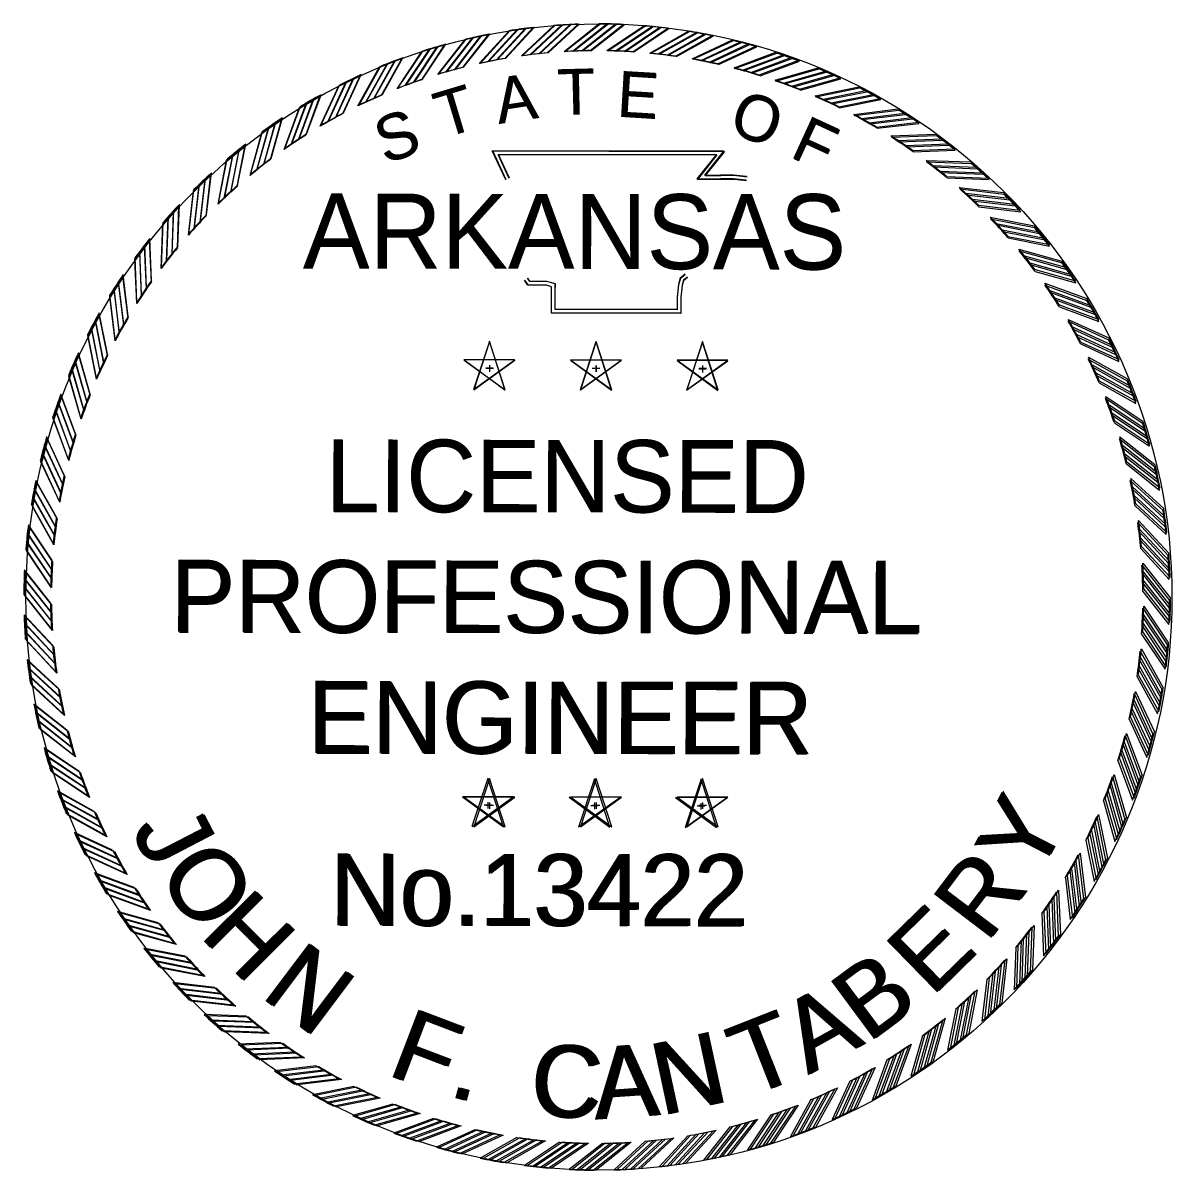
# Model space of a CAD drawing. Extents: x 759422 to 1467391, y 1662254 to 1691810.
# Drawn here: x 1467270.3 to 1467390.6, y 1691457.7 to 1691577.8 of the extents above; entities that cross this region are included whole.
import ezdxf

# ---------------------------------------------------------------- set-up
doc = ezdxf.new("R2010")
doc.units = 0
for name, color, linetype in [('Default', 7, 'Continuous'), ('G-ANNO-STMP', 7, 'Continuous'), ('G-No Plot-Stamp-1', 7, 'Continuous')]:
    doc.layers.add(name, color=color, linetype=linetype)

# ---------------------------------------------------------------- blocks, each defined once
blk = doc.blocks.new('STAR')
at = {"layer": 'Default'}
for p, q in [((-0.0001, 0.0615), (-0.0366, -0.0504)), ((0.0362, -0.0503), (0, 0.0617)), ((0.0587, 0.0188), (-0.059, 0.0189)), ((-0.0589, 0.0188), (0.0363, -0.0505)), ((-0.0365, -0.0503), (0.0589, 0.0188)), ((-0.0085, 0), (0.009, 0)), ((0, 0.0063), (0, -0.0085))]:
    blk.add_line(p, q, dxfattribs=at)
blk = doc.blocks.new('RP')
at = {"layer": 'Default'}
for p, q in [((-0.0781, 1.2656), (0.003, 1.33)), ((-0.058, 1.2667), (0.0216, 1.3299)), ((-0.0375, 1.2674), (0.0405, 1.3294)), ((-0.0176, 1.2679), (0.059, 1.3287))]:
    blk.add_line(p, q, dxfattribs=at)
for radius, start, end in [(1.33, 87.4562, 89.8699), (1.268, 90.7933, 93.5307)]:
    blk.add_arc((0, 0), radius, start, end, dxfattribs=at)

msp = doc.modelspace()

# ---------------------------------------------------------------- linework, layer by layer
at = {"layer": 'G-ANNO-STMP'}
for points in [[(1467320.82, 1691561.41), (1467319.42, 1691564.45), (1467343.68, 1691564.46), (1467341.65, 1691561.91), (1467343.3, 1691561.93), (1467344.67, 1691561.95), (1467346.05, 1691561.8)], [(1467320.86, 1691561.43), (1467319.47, 1691564.47), (1467343.73, 1691564.4), (1467341.7, 1691561.86), (1467343.35, 1691561.87), (1467344.72, 1691561.89), (1467346.1, 1691561.73)], [(1467321.17, 1691561.57), (1467320.02, 1691564.06), (1467342.88, 1691564.07), (1467340.84, 1691561.52), (1467343.3, 1691561.55), (1467344.65, 1691561.57), (1467346.01, 1691561.42)], [(1467321.21, 1691561.59), (1467320.07, 1691564.08), (1467342.93, 1691564.02), (1467340.89, 1691561.47), (1467343.35, 1691561.49), (1467344.7, 1691561.5), (1467346.05, 1691561.35)], [(1467339.85, 1691551.24), (1467339.44, 1691550.91), (1467339.3, 1691550.4), (1467339.16, 1691549.14), (1467339.16, 1691547.47), (1467325.62, 1691547.47), (1467325.62, 1691549.73), (1467325.62, 1691550.23), (1467325.07, 1691550.4), (1467323.15, 1691550.4), (1467322.8, 1691550.92)], [(1467339.87, 1691551.19), (1467339.45, 1691550.86), (1467339.31, 1691550.36), (1467339.17, 1691549.1), (1467339.16, 1691547.42), (1467325.62, 1691547.47), (1467325.63, 1691549.73), (1467325.63, 1691550.23), (1467325.08, 1691550.4), (1467323.16, 1691550.41), (1467322.82, 1691550.93)], [(1467339.61, 1691551.54), (1467339.1, 1691551.13), (1467338.92, 1691550.47), (1467338.78, 1691549.17), (1467338.78, 1691547.85), (1467326.01, 1691547.85), (1467326.01, 1691549.73), (1467326.01, 1691550.52), (1467325.13, 1691550.79), (1467323.35, 1691550.79), (1467323.12, 1691551.14)], [(1467339.62, 1691551.49), (1467339.11, 1691551.08), (1467338.93, 1691550.43), (1467338.79, 1691549.12), (1467338.78, 1691547.81), (1467326.01, 1691547.85), (1467326.01, 1691549.73), (1467326.02, 1691550.52), (1467325.14, 1691550.79), (1467323.36, 1691550.79), (1467323.14, 1691551.14)]]:
    msp.add_lwpolyline(points, dxfattribs=at)
at = {"layer": 'G-No Plot-Stamp-1'}
msp.add_circle((1467330.59, 1691517.75), 60, dxfattribs=at)

# ---------------------------------------------------------------- block references
at = {"layer": 'G-ANNO-STMP'}
for name, p, xscale, yscale, rotation in [('RP', (1467330.45, 1691517.76), 45.10357918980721, 45.10357918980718, 4.500000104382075), ('RP', (1467330.35, 1691517.74), 45.1035791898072, 45.10357918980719, 4.304199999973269), ('RP', (1467330.45, 1691517.76), 45.1035791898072, 45.10357918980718, 1.0438208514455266e-07), ('RP', (1467330.35, 1691517.74), 45.1035791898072, 45.10357918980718, -0.19580000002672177), ('RP', (1467330.45, 1691517.76), 45.103579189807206, 45.10357918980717, -4.499999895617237), ('RP', (1467330.35, 1691517.74), 45.103579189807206, 45.10357918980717, -4.695800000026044), ('RP', (1467330.45, 1691517.76), 45.10357918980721, 45.103579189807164, -8.999999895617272), ('RP', (1467330.35, 1691517.74), 45.10357918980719, 45.103579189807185, -9.19580000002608), ('RP', (1467330.45, 1691517.76), 45.10357918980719, 45.10357918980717, 13.500000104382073), ('RP', (1467330.35, 1691517.74), 45.1035791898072, 45.103579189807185, 13.304199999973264), ('RP', (1467330.45, 1691517.76), 45.103579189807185, 45.103579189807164, 9.000000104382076), ('RP', (1467330.35, 1691517.74), 45.10357918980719, 45.103579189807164, 8.804199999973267), ('RP', (1467330.45, 1691517.76), 45.10357918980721, 45.10357918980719, -13.499999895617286), ('RP', (1467330.35, 1691517.74), 45.103579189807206, 45.103579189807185, -13.695800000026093), ('RP', (1467330.45, 1691517.76), 45.103579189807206, 45.10357918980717, 18.00000010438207), ('RP', (1467330.35, 1691517.74), 45.1035791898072, 45.10357918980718, 17.804199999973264), ('RP', (1467330.45, 1691517.76), 45.103579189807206, 45.103579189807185, -17.999999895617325), ('RP', (1467330.35, 1691517.74), 45.1035791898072, 45.10357918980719, -18.19580000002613), ('RP', (1467330.45, 1691517.76), 45.1035791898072, 45.10357918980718, 22.500000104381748), ('RP', (1467330.35, 1691517.74), 45.1035791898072, 45.10357918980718, 22.304199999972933), ('RP', (1467330.45, 1691517.76), 45.103579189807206, 45.10357918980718, -22.499999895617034), ('RP', (1467330.35, 1691517.74), 45.10357918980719, 45.103579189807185, -22.695800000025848), ('RP', (1467330.45, 1691517.76), 45.10357918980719, 45.103579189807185, -26.999999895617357), ('RP', (1467330.35, 1691517.74), 45.1035791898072, 45.10357918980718, -27.19580000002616), ('RP', (1467330.45, 1691517.76), 45.1035791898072, 45.10357918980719, 27.000000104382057), ('RP', (1467330.35, 1691517.74), 45.1035791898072, 45.103579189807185, 26.80419999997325), ('RP', (1467330.45, 1691517.76), 45.10357918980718, 45.103579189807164, 31.50000010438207), ('RP', (1467330.35, 1691517.74), 45.10357918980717, 45.103579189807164, 31.30419999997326), ('RP', (1467330.45, 1691517.76), 45.10357918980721, 45.1035791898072, -31.49999989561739), ('RP', (1467330.35, 1691517.74), 45.103579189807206, 45.1035791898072, -31.695800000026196), ('RP', (1467330.45, 1691517.76), 45.10357918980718, 45.103579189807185, 36.00000010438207), ('RP', (1467330.35, 1691517.74), 45.10357918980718, 45.10357918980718, 35.804199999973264), ('RP', (1467330.45, 1691517.76), 45.10357918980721, 45.10357918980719, -35.999999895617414), ('RP', (1467330.35, 1691517.74), 45.1035791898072, 45.10357918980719, -36.195800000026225), ('RP', (1467330.45, 1691517.76), 45.1035791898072, 45.1035791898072, -40.49999989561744), ('RP', (1467330.35, 1691517.74), 45.1035791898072, 45.10357918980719, -40.69580000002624), ('RP', (1467330.45, 1691517.76), 45.103579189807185, 45.10357918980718, 40.50000010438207), ('RP', (1467330.35, 1691517.74), 45.103579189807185, 45.10357918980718, 40.30419999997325), ('RP', (1467330.45, 1691517.76), 45.10357918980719, 45.10357918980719, 45.00000010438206), ('RP', (1467330.35, 1691517.74), 45.103579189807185, 45.10357918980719, 44.80419999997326), ('RP', (1467330.45, 1691517.76), 45.1035791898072, 45.10357918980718, -44.99999989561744), ('RP', (1467330.35, 1691517.74), 45.103579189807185, 45.10357918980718, -45.19580000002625), ('RP', (1467330.45, 1691517.76), 45.10357918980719, 45.103579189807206, 49.500000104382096), ('RP', (1467330.35, 1691517.74), 45.103579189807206, 45.1035791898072, 49.304199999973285), ('RP', (1467330.45, 1691517.76), 45.103579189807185, 45.10357918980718, -49.499999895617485), ('RP', (1467330.35, 1691517.74), 45.10357918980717, 45.103579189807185, -49.695800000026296), ('RP', (1467330.45, 1691517.76), 45.10357918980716, 45.10357918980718, -53.999999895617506), ('RP', (1467330.45, 1691517.76), 45.103579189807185, 45.10357918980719, 54.00000010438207), ('RP', (1467330.35, 1691517.74), 45.10357918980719, 45.103579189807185, 53.804199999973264), ('RP', (1467330.35, 1691517.74), 45.103579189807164, 45.10357918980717, -54.1958000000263), ('RP', (1467330.35, 1691517.74), 45.10357918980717, 45.103579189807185, 58.304199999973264), ('RP', (1467330.45, 1691517.76), 45.10357918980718, 45.10357918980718, 58.50000010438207), ('RP', (1467330.45, 1691517.76), 45.103579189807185, 45.10357918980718, -58.49999989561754), ('RP', (1467330.35, 1691517.74), 45.10357918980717, 45.103579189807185, -58.695800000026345), ('RP', (1467330.35, 1691517.74), 45.103579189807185, 45.103579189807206, 62.804199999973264), ('RP', (1467330.45, 1691517.76), 45.10357918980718, 45.10357918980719, -62.99999989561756), ('RP', (1467330.35, 1691517.74), 45.103579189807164, 45.10357918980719, -63.19580000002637), ('RP', (1467330.45, 1691517.76), 45.10357918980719, 45.1035791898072, 63.000000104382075), ('STAR', (1467319.11, 1691541.73), 45.1035791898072, 45.10357918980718, -0.19580000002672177), ('STAR', (1467319.13, 1691541.71), 45.1035791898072, 45.10357918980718, 1.0438208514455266e-07), ('STAR', (1467330.27, 1691541.69), 45.1035791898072, 45.10357918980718, -0.19580000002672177), ('STAR', (1467330.29, 1691541.71), 45.1035791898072, 45.10357918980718, 1.0438208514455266e-07), ('STAR', (1467341.42, 1691541.65), 45.1035791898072, 45.10357918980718, -0.19580000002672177), ('STAR', (1467341.44, 1691541.71), 45.1035791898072, 45.10357918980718, 1.0438208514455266e-07), ('RP', (1467330.45, 1691517.76), 45.10357918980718, 45.1035791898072, -67.49999989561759), ('RP', (1467330.35, 1691517.74), 45.10357918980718, 45.1035791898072, 67.30419999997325), ('RP', (1467330.45, 1691517.76), 45.10357918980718, 45.103579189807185, 67.50000010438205), ('RP', (1467330.35, 1691517.74), 45.10357918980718, 45.103579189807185, -67.69580000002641), ('RP', (1467330.35, 1691517.74), 45.103579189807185, 45.1035791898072, 71.80419999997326), ('RP', (1467330.35, 1691517.74), 45.10357918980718, 45.1035791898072, -72.19580000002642), ('RP', (1467330.45, 1691517.76), 45.10357918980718, 45.1035791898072, -71.99999989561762), ('RP', (1467330.45, 1691517.76), 45.103579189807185, 45.10357918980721, 72.00000010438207), ('RP', (1467330.35, 1691517.74), 45.10357918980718, 45.1035791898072, 76.30419999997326), ('RP', (1467330.45, 1691517.76), 45.103579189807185, 45.103579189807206, 76.50000010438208), ('RP', (1467330.35, 1691517.74), 45.10357918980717, 45.10357918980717, -76.69580000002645), ('RP', (1467330.45, 1691517.76), 45.103579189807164, 45.10357918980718, -76.49999989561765), ('RP', (1467330.45, 1691517.76), 45.10357918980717, 45.1035791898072, -80.99999989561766), ('RP', (1467330.35, 1691517.74), 45.10357918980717, 45.10357918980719, 80.80419999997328), ('RP', (1467330.45, 1691517.76), 45.10357918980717, 45.10357918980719, 81.0000001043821), ('RP', (1467330.35, 1691517.74), 45.10357918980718, 45.1035791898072, -81.19580000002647), ('RP', (1467330.35, 1691517.74), 45.103579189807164, 45.10357918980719, -85.69580000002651), ('RP', (1467330.45, 1691517.76), 45.10357918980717, 45.103579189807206, -85.49999989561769), ('RP', (1467330.35, 1691517.74), 45.10357918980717, 45.10357918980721, 85.30419999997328), ('RP', (1467330.45, 1691517.76), 45.10357918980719, 45.1035791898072, 85.50000010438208), ('RP', (1467330.35, 1691517.74), 45.10357918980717, 45.103579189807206, -90.19580000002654), ('RP', (1467330.45, 1691517.76), 45.10357918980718, 45.10357918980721, -89.99999989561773), ('RP', (1467330.35, 1691517.74), 45.10357918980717, 45.103579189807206, 89.80419999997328), ('RP', (1467330.45, 1691517.76), 45.103579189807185, 45.10357918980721, 90.0000001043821), ('RP', (1467330.35, 1691517.74), 45.10357918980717, 45.10357918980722, 94.30419999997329), ('RP', (1467330.35, 1691517.74), 45.10357918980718, 45.103579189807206, -94.69580000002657), ('RP', (1467330.45, 1691517.76), 45.103579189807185, 45.10357918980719, -94.49999989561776), ('RP', (1467330.45, 1691517.76), 45.103579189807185, 45.10357918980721, 94.5000001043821), ('RP', (1467330.35, 1691517.74), 45.10357918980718, 45.10357918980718, 98.8041999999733), ('RP', (1467330.45, 1691517.76), 45.10357918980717, 45.103579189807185, 99.0000001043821), ('RP', (1467330.35, 1691517.74), 45.10357918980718, 45.1035791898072, -99.19580000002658), ('RP', (1467330.45, 1691517.76), 45.10357918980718, 45.1035791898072, -98.99999989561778), ('RP', (1467330.45, 1691517.76), 45.103579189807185, 45.10357918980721, -103.4999998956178), ('RP', (1467330.35, 1691517.74), 45.10357918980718, 45.1035791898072, 103.30419999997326), ('RP', (1467330.45, 1691517.76), 45.10357918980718, 45.1035791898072, 103.50000010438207), ('RP', (1467330.35, 1691517.74), 45.10357918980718, 45.1035791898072, -103.69580000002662), ('RP', (1467330.35, 1691517.74), 45.10357918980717, 45.1035791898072, -108.19580000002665), ('RP', (1467330.45, 1691517.76), 45.10357918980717, 45.1035791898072, -107.99999989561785), ('RP', (1467330.35, 1691517.74), 45.10357918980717, 45.10357918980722, 107.80419999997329), ('RP', (1467330.45, 1691517.76), 45.10357918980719, 45.10357918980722, 108.0000001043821), ('RP', (1467330.35, 1691517.74), 45.10357918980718, 45.103579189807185, 112.30419999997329), ('RP', (1467330.45, 1691517.76), 45.10357918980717, 45.1035791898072, 112.5000001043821), ('STAR', (1467318.95, 1691495.98), 45.1035791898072, 45.10357918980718, -0.19580000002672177), ('STAR', (1467319.13, 1691495.96), 45.1035791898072, 45.10357918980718, 1.0438208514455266e-07), ('STAR', (1467330.11, 1691495.94), 45.1035791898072, 45.10357918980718, -0.19580000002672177), ('STAR', (1467330.29, 1691495.96), 45.1035791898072, 45.10357918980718, 1.0438208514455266e-07), ('STAR', (1467341.27, 1691495.9), 45.1035791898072, 45.10357918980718, -0.19580000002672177), ('STAR', (1467341.44, 1691495.96), 45.1035791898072, 45.10357918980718, 1.0438208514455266e-07), ('RP', (1467330.35, 1691517.74), 45.10357918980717, 45.103579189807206, -112.69580000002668), ('RP', (1467330.45, 1691517.76), 45.10357918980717, 45.10357918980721, -112.49999989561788), ('RP', (1467330.35, 1691517.74), 45.10357918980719, 45.103579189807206, -117.19580000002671), ('RP', (1467330.45, 1691517.76), 45.1035791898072, 45.103579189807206, -116.9999998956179), ('RP', (1467330.35, 1691517.74), 45.103579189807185, 45.1035791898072, 116.80419999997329), ('RP', (1467330.45, 1691517.76), 45.10357918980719, 45.1035791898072, 117.0000001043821), ('RP', (1467330.45, 1691517.76), 45.10357918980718, 45.103579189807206, -121.4999998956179), ('RP', (1467330.35, 1691517.74), 45.103579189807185, 45.103579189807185, 121.30419999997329), ('RP', (1467330.45, 1691517.76), 45.103579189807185, 45.10357918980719, 121.5000001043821), ('RP', (1467330.35, 1691517.74), 45.10357918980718, 45.103579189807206, -121.69580000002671), ('RP', (1467330.35, 1691517.74), 45.10357918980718, 45.10357918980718, 125.80419999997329), ('RP', (1467330.45, 1691517.76), 45.10357918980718, 45.103579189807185, 126.00000010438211), ('RP', (1467330.35, 1691517.74), 45.10357918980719, 45.1035791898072, -126.19580000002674), ('RP', (1467330.45, 1691517.76), 45.103579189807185, 45.103579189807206, -125.99999989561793), ('RP', (1467330.35, 1691517.74), 45.10357918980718, 45.103579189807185, 130.3041999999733), ('RP', (1467330.45, 1691517.76), 45.103579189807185, 45.10357918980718, 130.50000010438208), ('RP', (1467330.35, 1691517.74), 45.103579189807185, 45.10357918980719, -130.6958000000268), ('RP', (1467330.45, 1691517.76), 45.103579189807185, 45.10357918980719, -130.49999989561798), ('RP', (1467330.35, 1691517.74), 45.10357918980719, 45.103579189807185, 134.80419999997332), ('RP', (1467330.45, 1691517.76), 45.1035791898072, 45.103579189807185, 135.00000010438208), ('RP', (1467330.35, 1691517.74), 45.103579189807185, 45.10357918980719, -135.19580000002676), ('RP', (1467330.45, 1691517.76), 45.10357918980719, 45.10357918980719, -134.99999989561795), ('RP', (1467330.35, 1691517.74), 45.10357918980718, 45.103579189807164, -139.69580000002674), ('RP', (1467330.45, 1691517.76), 45.103579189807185, 45.10357918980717, -139.49999989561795), ('RP', (1467330.35, 1691517.74), 45.10357918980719, 45.103579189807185, 139.30419999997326), ('RP', (1467330.45, 1691517.76), 45.10357918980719, 45.103579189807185, 139.50000010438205), ('RP', (1467330.35, 1691517.74), 45.103579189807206, 45.103579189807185, 143.8041999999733), ('RP', (1467330.45, 1691517.76), 45.103579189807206, 45.103579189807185, 144.00000010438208), ('RP', (1467330.35, 1691517.74), 45.103579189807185, 45.103579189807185, -144.19580000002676), ('RP', (1467330.45, 1691517.76), 45.1035791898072, 45.10357918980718, -143.99999989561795), ('RP', (1467330.35, 1691517.74), 45.10357918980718, 45.10357918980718, 148.3041999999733), ('RP', (1467330.45, 1691517.76), 45.103579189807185, 45.10357918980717, 148.50000010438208), ('RP', (1467330.35, 1691517.74), 45.10357918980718, 45.10357918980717, -148.69580000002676), ('RP', (1467330.45, 1691517.76), 45.10357918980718, 45.103579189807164, -148.49999989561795), ('RP', (1467330.35, 1691517.74), 45.10357918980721, 45.103579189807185, 152.8041999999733), ('RP', (1467330.45, 1691517.76), 45.10357918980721, 45.1035791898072, 153.00000010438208), ('RP', (1467330.35, 1691517.74), 45.103579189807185, 45.10357918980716, -153.1958000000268), ('RP', (1467330.45, 1691517.76), 45.10357918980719, 45.103579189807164, -152.99999989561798), ('RP', (1467330.35, 1691517.74), 45.1035791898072, 45.10357918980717, 157.3041999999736), ('RP', (1467330.45, 1691517.76), 45.103579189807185, 45.10357918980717, 157.50000010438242), ('RP', (1467330.35, 1691517.74), 45.1035791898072, 45.103579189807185, -157.6958000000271), ('RP', (1467330.45, 1691517.76), 45.10357918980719, 45.10357918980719, -157.4999998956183), ('RP', (1467330.35, 1691517.74), 45.1035791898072, 45.10357918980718, -162.19580000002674), ('RP', (1467330.45, 1691517.76), 45.103579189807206, 45.103579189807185, -161.99999989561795), ('RP', (1467330.35, 1691517.74), 45.103579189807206, 45.10357918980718, 161.8041999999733), ('RP', (1467330.45, 1691517.76), 45.10357918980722, 45.103579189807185, 162.00000010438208), ('RP', (1467330.35, 1691517.74), 45.103579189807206, 45.10357918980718, 166.3041999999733), ('RP', (1467330.45, 1691517.76), 45.103579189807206, 45.10357918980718, 166.50000010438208), ('RP', (1467330.35, 1691517.74), 45.1035791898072, 45.10357918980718, -166.69580000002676), ('RP', (1467330.45, 1691517.76), 45.10357918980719, 45.103579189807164, -166.49999989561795), ('RP', (1467330.35, 1691517.74), 45.1035791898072, 45.10357918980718, 170.8041999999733), ('RP', (1467330.45, 1691517.76), 45.1035791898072, 45.10357918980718, 171.00000010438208), ('RP', (1467330.35, 1691517.74), 45.103579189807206, 45.10357918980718, 175.3041999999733), ('RP', (1467330.45, 1691517.76), 45.10357918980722, 45.10357918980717, 175.50000010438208), ('RP', (1467330.35, 1691517.74), 45.10357918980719, 45.103579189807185, -175.69580000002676), ('RP', (1467330.45, 1691517.76), 45.1035791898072, 45.10357918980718, -175.49999989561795), ('RP', (1467330.35, 1691517.74), 45.10357918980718, 45.10357918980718, -171.19580000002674), ('RP', (1467330.45, 1691517.76), 45.103579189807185, 45.103579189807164, -170.99999989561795), ('RP', (1467330.35, 1691517.74), 45.1035791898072, 45.10357918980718, 179.8041999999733), ('RP', (1467330.45, 1691517.76), 45.10357918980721, 45.103579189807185, -179.99999989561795)]:
    msp.add_blockref(name, p, dxfattribs=dict(at, xscale=xscale, yscale=yscale, rotation=rotation))

# ---------------------------------------------------------------- texts
for s, height, rotation, p in [('T', 4.79, 1.4789, (1467326.26, 1691568.2)), ('T', 4.79, 1.2831, (1467326.33, 1691568.2)), ('E', 4.79, 356.672, (1467332.38, 1691568.06)), ('E', 4.79, 356.4762, (1467332.45, 1691568.03)), ('A', 4.79, 8.6788, (1467320.08, 1691567.25)), ('A', 4.79, 8.483, (1467320.15, 1691567.27)), ('T', 4.79, 16.9015, (1467314.27, 1691565.73)), ('T', 4.79, 16.7057, (1467314.33, 1691565.77)), ('O', 4.79, 341.2218, (1467344, 1691566.41)), ('O', 4.79, 341.026, (1467344.07, 1691566.35)), ('S', 4.79, 19.7726, (1467308.18, 1691563)), ('S', 4.79, 19.5768, (1467308.24, 1691563.06)), ('F', 4.79, 335.3628, (1467350.45, 1691563.89)), ('F', 4.79, 335.167, (1467350.51, 1691563.81)), ('ARKANSAS', 7.81, 0, (1467299.58, 1691552.11)), ('ARKANSAS', 7.81, 359.8042, (1467299.6, 1691552.2)), ('LICENSED', 7.561, 359.8042, (1467301.94, 1691526.7)), ('LICENSED', 7.561, 0, (1467302.01, 1691526.62)), ('PROFESSIONAL', 7.5612, 359.8042, (1467285.69, 1691514.11)), ('PROFESSIONAL', 7.5612, 0, (1467285.81, 1691513.98)), ('ENGINEER', 7.561, 359.8042, (1467300.05, 1691501.42)), ('ENGINEER', 7.561, 0, (1467300.21, 1691501.33)), ('Y', 7.56, 62.5392, (1467376.45, 1691488.07)), ('Y', 7.56, 62.735, (1467376.65, 1691488.24)), ('J', 7.56, 297.2813, (1467281.48, 1691493.44)), ('J', 7.56, 297.4771, (1467281.66, 1691493.29)), ('O', 7.56, 304.1899, (1467284.16, 1691488.8)), ('O', 7.56, 304.3857, (1467284.36, 1691488.66)), ('No.13422', 7.531, 359.8042, (1467302.38, 1691483.39)), ('No.13422', 7.531, 0, (1467302.6, 1691483.31)), ('R', 7.56, 52.7437, (1467371.17, 1691481.41)), ('R', 7.56, 52.9395, (1467371.39, 1691481.56)), ('H', 7.56, 314.7447, (1467288.62, 1691482.29)), ('H', 7.56, 314.9405, (1467288.84, 1691482.16)), ('E', 7.56, 44.306, (1467365.41, 1691475.78)), ('E', 7.56, 44.5018, (1467365.65, 1691475.92)), ('N', 7.56, 322.9417, (1467295, 1691475.96)), ('N', 7.56, 323.1375, (1467295.24, 1691475.86)), ('B', 7.56, 36.505, (1467358.73, 1691470.97)), ('B', 7.56, 36.7008, (1467359, 1691471.08)), ('A', 7.56, 28.8562, (1467352.45, 1691467.67)), ('A', 7.56, 29.052, (1467352.73, 1691467.76)), ('F', 7.56, 339.0288, (1467308.2, 1691467.78)), ('F', 7.56, 339.2246, (1467308.47, 1691467.72)), ('T', 7.56, 21.4329, (1467346.17, 1691465.3)), ('T', 7.56, 21.6287, (1467346.45, 1691465.37)), ('N', 7.56, 12.0703, (1467337.05, 1691463.42)), ('N', 7.56, 12.2661, (1467337.33, 1691463.46)), ('C', 7.56, 356.1028, (1467323.2, 1691463.53)), ('C', 7.56, 356.2986, (1467323.49, 1691463.52)), ('A', 7.56, 3.9092, (1467330.13, 1691463.03)), ('A', 7.56, 4.105, (1467330.42, 1691463.05)), ('.', 7.56, 344.7037, (1467314.65, 1691465.54)), ('.', 7.56, 344.8995, (1467314.93, 1691465.5))]:
    msp.add_text(s, height=height, rotation=rotation, dxfattribs=at).set_placement(p)

doc.saveas('drawing.dxf')
